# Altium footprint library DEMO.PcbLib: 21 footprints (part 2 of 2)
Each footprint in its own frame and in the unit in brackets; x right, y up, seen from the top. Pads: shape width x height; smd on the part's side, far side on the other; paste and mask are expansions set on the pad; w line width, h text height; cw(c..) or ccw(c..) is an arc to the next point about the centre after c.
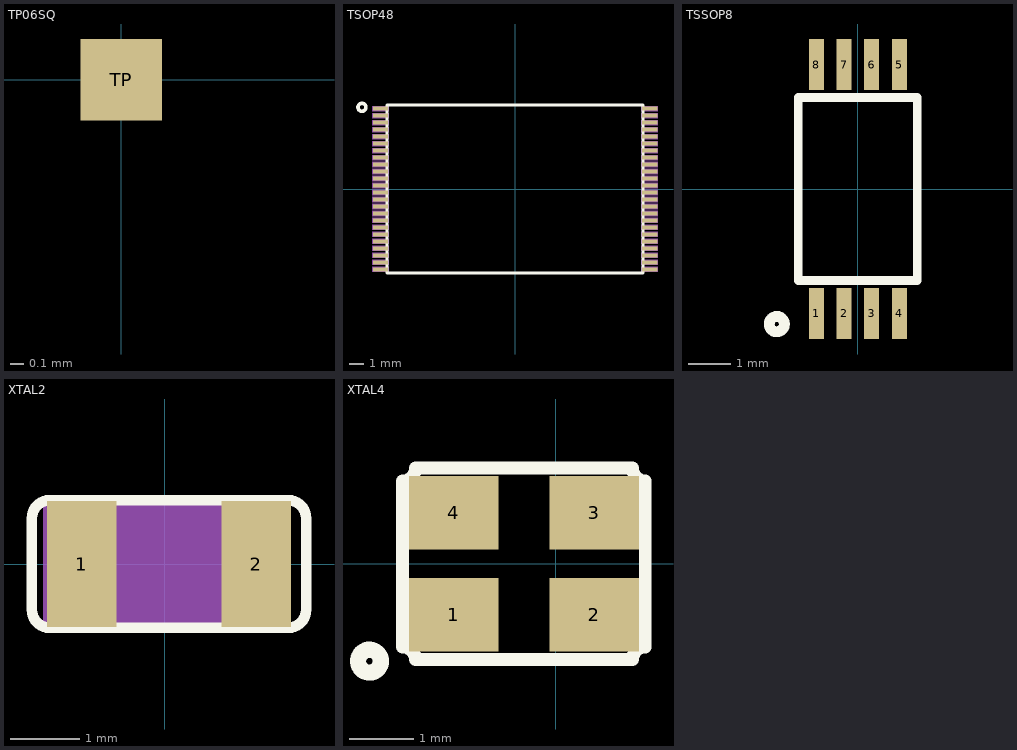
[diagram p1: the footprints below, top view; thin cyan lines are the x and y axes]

## TP06SQ [mm]
height 3
pads (1):
  rect 0.6x0.6 smd: TP(0,0)
Top Overlay:

## TSOP48 [mm]
pads (48):
  rect 1.1x0.3 smd: 1(-9.625,5.75) 2(-9.625,5.25) 3(-9.625,4.75) 4(-9.625,4.25) 5(-9.625,3.75) 6(-9.625,3.25) 7(-9.625,2.75) 8(-9.625,2.25) 9(-9.625,1.75) 10(-9.625,1.25) 11(-9.625,0.75) 12(-9.625,0.25) 13(-9.625,-0.25) 14(-9.625,-0.75) 15(-9.625,-1.25) 16(-9.625,-1.75) 17(-9.625,-2.25) 18(-9.625,-2.75) 19(-9.625,-3.25) 20(-9.625,-3.75) 21(-9.625,-4.25) 22(-9.625,-4.75) 23(-9.625,-5.25) 24(-9.625,-5.75) 25(9.625,-5.75) 26(9.625,-5.25) 27(9.625,-4.75) 28(9.625,-4.25) 29(9.625,-3.75) 30(9.625,-3.25) 31(9.625,-2.75) 32(9.625,-2.25) 33(9.625,-1.75) 34(9.625,-1.25) 35(9.625,-0.75) 36(9.625,-0.25) 37(9.625,0.25) 38(9.625,0.75) 39(9.625,1.25) 40(9.625,1.75) 41(9.625,2.25) 42(9.625,2.75) 43(9.625,3.25) 44(9.625,3.75) 45(9.625,4.25) 46(9.625,4.75) 47(9.625,5.25) 48(9.625,5.75)
Top Overlay:
  circle w0.254: c-10.952,5.842 r0.284
  lines w0.203: -9.15,-6 9.15,-6 9.15,6 -9.15,6 -9.15,-6
Mechanical 4:
  rectangle: -10.225,5.55 -9.025,5.95
  rectangle: -10.225,5.05 -9.025,5.45
  rectangle: -10.225,4.55 -9.025,4.95
  rectangle: -10.225,4.05 -9.025,4.45
  rectangle: -10.225,3.55 -9.025,3.95
  rectangle: -10.225,3.05 -9.025,3.45
  rectangle: -10.225,2.55 -9.025,2.95
  rectangle: -10.225,2.05 -9.025,2.45
  rectangle: -10.225,1.55 -9.025,1.95
  rectangle: -10.225,1.05 -9.025,1.45
  rectangle: -10.225,0.55 -9.025,0.95
  rectangle: -10.225,0.05 -9.025,0.45
  rectangle: -10.225,-0.45 -9.025,-0.05
  rectangle: -10.225,-0.95 -9.025,-0.55
  rectangle: -10.225,-1.45 -9.025,-1.05
  rectangle: -10.225,-1.95 -9.025,-1.55
  rectangle: -10.225,-2.45 -9.025,-2.05
  rectangle: -10.225,-2.95 -9.025,-2.55
  rectangle: -10.225,-3.45 -9.025,-3.05
  rectangle: -10.225,-3.95 -9.025,-3.55
  rectangle: -10.225,-4.45 -9.025,-4.05
  rectangle: -10.225,-4.95 -9.025,-4.55
  rectangle: -10.225,-5.45 -9.025,-5.05
  rectangle: -10.225,-5.95 -9.025,-5.55
  region: 10.225,-5.55 9.025,-5.55 9.025,-5.95 10.225,-5.95
  region: 10.225,-5.05 9.025,-5.05 9.025,-5.45 10.225,-5.45
  region: 10.225,-4.55 9.025,-4.55 9.025,-4.95 10.225,-4.95
  region: 10.225,-4.05 9.025,-4.05 9.025,-4.45 10.225,-4.45
  region: 10.225,-3.55 9.025,-3.55 9.025,-3.95 10.225,-3.95
  region: 10.225,-3.05 9.025,-3.05 9.025,-3.45 10.225,-3.45
  region: 10.225,-2.55 9.025,-2.55 9.025,-2.95 10.225,-2.95
  region: 10.225,-2.05 9.025,-2.05 9.025,-2.45 10.225,-2.45
  region: 10.225,-1.55 9.025,-1.55 9.025,-1.95 10.225,-1.95
  region: 10.225,-1.05 9.025,-1.05 9.025,-1.45 10.225,-1.45
  region: 10.225,-0.55 9.025,-0.55 9.025,-0.95 10.225,-0.95
  region: 10.225,-0.05 9.025,-0.05 9.025,-0.45 10.225,-0.45
  region: 10.225,0.45 9.025,0.45 9.025,0.05 10.225,0.05
  region: 10.225,0.95 9.025,0.95 9.025,0.55 10.225,0.55
  region: 10.225,1.45 9.025,1.45 9.025,1.05 10.225,1.05
  region: 10.225,1.95 9.025,1.95 9.025,1.55 10.225,1.55
  region: 10.225,2.45 9.025,2.45 9.025,2.05 10.225,2.05
  region: 10.225,2.95 9.025,2.95 9.025,2.55 10.225,2.55
  region: 10.225,3.45 9.025,3.45 9.025,3.05 10.225,3.05
  region: 10.225,3.95 9.025,3.95 9.025,3.55 10.225,3.55
  region: 10.225,4.45 9.025,4.45 9.025,4.05 10.225,4.05
  region: 10.225,4.95 9.025,4.95 9.025,4.55 10.225,4.55
  region: 10.225,5.45 9.025,5.45 9.025,5.05 10.225,5.05
  region: 10.225,5.95 9.025,5.95 9.025,5.55 10.225,5.55

## TSSOP8 [mm]
pads (8):
  rect 0.35x1.2 smd: 1(-0.975,-2.925) 2(-0.325,-2.925) 3(0.325,-2.925) 4(0.975,-2.925) 5(0.975,2.925) 6(0.325,2.925) 7(-0.325,2.925) 8(-0.975,2.925)
Top Overlay:
  circle w0.254: c-1.905,-3.175 r0.18
  lines w0.203: -1.4,-2.15 1.4,-2.15 1.4,2.15 -1.4,2.15 -1.4,-2.15

## XTAL2 [mm]
height 3
pads (2):
  rect 1x1.8 smd: 1(-1.19,0) 2(1.31,0)
Top Overlay:
  lines w0.152: -1.905,-0.659 ccw(c-1.651,-0.659) -1.651,-0.913 1.771,-0.913 ccw(c1.771,-0.659) 2.025,-0.659 ; -1.905,-0.643 -1.905,0.643 ; -1.905,0.659 cw(c-1.651,0.659) -1.651,0.913 1.771,0.913 cw(c1.771,0.659) 2.025,0.659 ; 2.025,-0.643 2.025,0.643
Mechanical 14:
  rectangle: -1.743,-0.9 1.758,0.9

## XTAL4 [mm]
pads (4):
  rect 1.4x1.15 smd: 1(-1.6,-0.8) 2(0.6,-0.8) 3(0.6,0.8) 4(-1.6,0.8)
Top Overlay:
  circle w0.254: c-2.921,-1.524 r0.18
  lines w0.203: -2.4,-1.3 cw(c-2.4,-1.5) -2.2,-1.5 1.2,-1.5 cw(c1.4,-1.5) 1.4,-1.3 1.4,1.3 cw(c1.4,1.5) 1.2,1.5 -2.2,1.5 cw(c-2.4,1.5) -2.4,1.3 -2.4,-1.3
